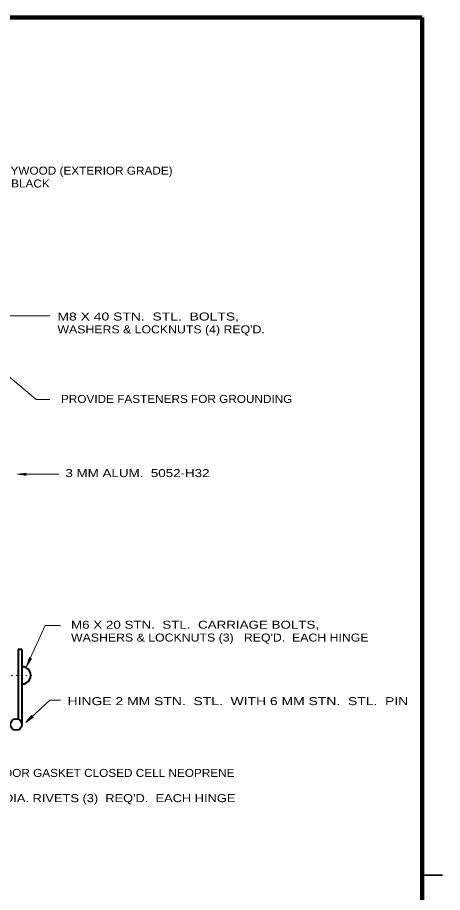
# Model space of a CAD drawing. Extents: x 312583 to 312853, y 144420 to 144585.
# Drawn here: x 312810.5 to 312850.9, y 144502 to 144585.1 of the extents above; entities that cross this region are included whole.
import ezdxf

# ---------------------------------------------------------------- set-up
doc = ezdxf.new("R2010")
doc.units = 0
doc.header["$LTSCALE"] = 0.3
doc.linetypes.add('DOTTED', pattern=[1.5, 0.3, -1.2])
doc.layers.add('1', color=7, linetype='Continuous', lineweight=40)
doc.layers.add('2', color=7, linetype='Continuous', lineweight=13)

msp = doc.modelspace()

# ---------------------------------------------------------------- linework, layer by layer
at = {"layer": '1', "lineweight": 158}
msp.add_line((312849, 144423.1446), (312849, 144585.0846), dxfattribs=at)
at = {"layer": '1'}
for p, q in [((312810.9669, 144525.0401), (312810.5989, 144525.0401)), ((312810.5989, 144525.0401), (312810.5989, 144518.4391)), ((312810.9669, 144525.0401), (312810.9669, 144517.8488))]:
    msp.add_line(p, q, dxfattribs=at)
at = {"layer": '1', "linetype": 'DOTTED', "lineweight": 13}
msp.add_line((312807.1949, 144522.5714), (312812.1169, 144522.5714), dxfattribs=at)
at = {"layer": '1', "lineweight": 35}
msp.add_line((312849, 144503.6216), (312850.932, 144503.6216), dxfattribs=at)
at = {"layer": '1', "lineweight": 158}
msp.add_lwpolyline([(312616.5, 144423.1446), (312616.5, 144585.0846), (312849, 144585.0846)], dxfattribs=at)
at = {"layer": '1'}
msp.add_circle((312810.4214, 144517.9217), 0.5474, dxfattribs=at)
msp.add_arc((312810.9731, 144522.5959), 0.8211, 269.38614, 90.61167, dxfattribs=at)
at = {"layer": '2'}
for p, q in [((312809.4336, 144556.7494), (312813.6042, 144556.7494)), ((312809.6942, 144551.0224), (312812.3009, 144548.7991)), ((312812.3009, 144548.7991), (312813.6042, 144548.7991)), ((312810.5452, 144541.6998), (312811.4116, 144541.8071)), ((312810.5452, 144541.6998), (312814.4552, 144541.6998)), ((312810.5452, 144541.6998), (312811.4116, 144541.5924)), ((312811.4116, 144541.8071), (312811.1356, 144541.6998)), ((312811.4116, 144541.5924), (312811.1356, 144541.6998)), ((312811.4116, 144523.4378), (312813.1826, 144527.3248)), ((312813.1826, 144527.3248), (312814.6239, 144527.3248)), ((312811.4116, 144523.4378), (312811.6722, 144524.2734)), ((312811.4116, 144523.4378), (312811.8716, 144524.1814)), ((312811.6722, 144524.2734), (312811.6569, 144523.9744)), ((312811.8716, 144524.1814), (312811.6569, 144523.9744)), ((312811.3196, 144518.1094), (312813.6272, 144520.2254)), ((312813.6272, 144520.2254), (312814.6239, 144520.2254)), ((312811.3196, 144518.1094), (312811.8869, 144518.7764)), ((312811.3196, 144518.1094), (312812.0326, 144518.6154)), ((312811.8869, 144518.7764), (312811.7566, 144518.5081)), ((312812.0326, 144518.6154), (312811.7566, 144518.5081))]:
    msp.add_line(p, q, dxfattribs=at)

# ---------------------------------------------------------------- texts
for s, width, p in [('20 MM PLYWOOD (EXTERIOR GRADE)', 1.1, (312804.7834, 144570.1577)), ('PAINTED BLACK', 1.1, (312804.7834, 144568.9377)), ('M8 X 40 STN.  STL.  BOLTS,', 1.3, (312814.338, 144556.2994)), ("WASHERS & LOCKNUTS (4) REQ'D.", 1.15, (312814.338, 144555.0794)), ('PROVIDE FASTENERS FOR GROUNDING', 1.1, (312814.6755, 144548.4701)), ('3 MM ALUM.  5052-H32', 1.25, (312815.0958, 144541.4268)), ('M6 X 20 STN.  STL.  CARRIAGE BOLTS,', 1.25, (312815.6282, 144527.0227)), ("WASHERS & LOCKNUTS (3)   REQ'D.  EACH HINGE", 1.15, (312815.6282, 144525.8027)), ('HINGE 2 MM STN.  STL.  WITH 6 MM STN.  STL.  PIN', 1.3, (312815.3028, 144519.7638)), ('DOOR GASKET CLOSED CELL NEOPRENE', 1.1, (312808.3644, 144512.9458)), ("6 MM DIA. RIVETS (3)  REQ'D.  EACH HINGE", 1.2, (312805.8762, 144510.5491))]:
    msp.add_text(s, height=0.76, dxfattribs=dict(at, width=width)).set_placement(p)

doc.saveas('drawing.dxf')
